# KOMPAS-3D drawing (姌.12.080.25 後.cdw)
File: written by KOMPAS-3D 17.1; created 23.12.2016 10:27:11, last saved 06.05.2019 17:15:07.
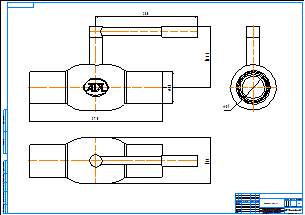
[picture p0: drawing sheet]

Sheet 1: A1, landscape

Title block, sheet 1: name: КШ.12.080.25 сс; material: Внимание! Данный продукт является объектом авторского права ООО «Торговый Дом АДЛ». / Запрещается изменение, копирование, распространение / (в том числе путем копирования на другие сайты и ресурсы в Интернете) / или любое иное использование информации и объектов без предварительного / согласия правообладателя (ООО «Торговый Дом АДЛ»).; sheets: 1; organisation: ООО "Торговый дом АДЛ"; sheet format: A1; stored path: C:\Users\tra\Desktop\2д чертежи\Шаровые краны БИВАЛ\КШ_Бивал_серия_11_12\KOMPAS_2D\КШ.12.080.25 сс.cdw

Views: Вид 1, Проекционный вид 2, Проекционный вид 3
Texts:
  Klimkovich
  ADL
Dimensions and other numbers on the sheet: 370; 89; 280; 168,8; 81; 127; 1:1; 1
